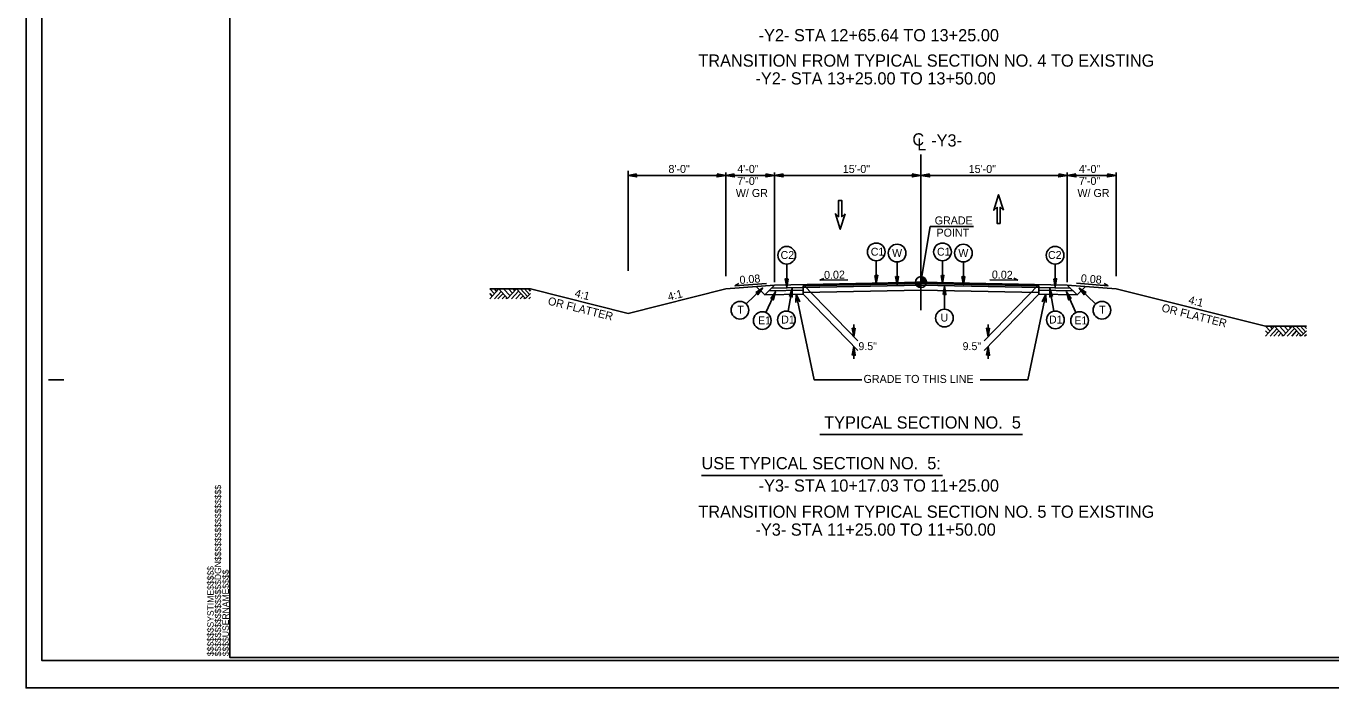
# Model space of a CAD drawing. Extents: x 1901718 to 1902220, y 193828 to 194187.
# Drawn here: x 1901965.8 to 1902072.8, y 193828 to 193882.3 of the extents above; entities that cross this region are included whole.
import ezdxf

# ---------------------------------------------------------------- set-up
doc = ezdxf.new("R2010")
doc.units = 0
for name, color, linetype in [('Old_Level_1', 7, 'Continuous'), ('Old_Level_11', 7, 'Continuous'), ('Old_Level_2', 7, 'Continuous'), ('Old_Level_20', 7, 'Continuous'), ('Old_Level_3', 7, 'Continuous'), ('Prop Dimension', 7, 'Continuous'), ('Sheet Border Standard 30in CELL', 7, 'Continuous'), ('Sheet Cutting Line CELL', 7, 'Continuous'), ('Sheet Plot Border Inside CELL', 7, 'Continuous'), ('Sheet Plot Border Outside CELL', 7, 'Continuous'), ('Typical Terminator CELL', 7, 'Continuous')]:
    doc.layers.add(name, color=color, linetype=linetype)

# ---------------------------------------------------------------- blocks, each defined once
blk = doc.blocks.new('TERMINATOR')
at = {"layer": 'Typical Terminator CELL'}
blk.add_lwpolyline([(-0.469, 0.081), (0, 0), (-0.471, -0.083), (-0.411, 0)], close=True, dxfattribs=at)

msp = doc.modelspace()

# ---------------------------------------------------------------- linework, layer by layer
at = {"layer": 'Old_Level_1'}
for p, q in [((1902039.18, 193858.97), (1902039.18, 193871.72)), ((1902015.18, 193870.02), (1902023.18, 193870.02)), ((1902023.18, 193861.77), (1902023.18, 193870.27)), ((1902023.18, 193870.02), (1902027.18, 193870.02)), ((1902027.18, 193861.27), (1902027.18, 193870.27)), ((1902027.18, 193870.02), (1902039.18, 193870.02)), ((1902051.18, 193870.02), (1902039.18, 193870.02)), ((1902051.18, 193861.27), (1902051.18, 193870.27)), ((1902055.18, 193870.02), (1902051.18, 193870.02)), ((1902055.18, 193861.77), (1902055.18, 193870.27)), ((1902027.18, 193861.03), (1902023.18, 193860.71)), ((1902026.52, 193861.17), (1902023.94, 193860.97)), ((1902023.94, 193860.97), (1902024.26, 193861.15)), ((1902026.38, 193860.23), (1902025.69, 193860.92)), ((1902027.18, 193861.03), (1902026.38, 193860.23)), ((1902029.53, 193860.83), (1902026.93, 193860.78)), ((1902039.18, 193861.27), (1902027.18, 193861.03)), ((1902039.18, 193861.17), (1902029.53, 193860.98)), ((1902029.53, 193861.08), (1902034, 193856.46)), ((1902039.18, 193861.02), (1902029.53, 193860.83)), ((1902029.53, 193860.98), (1902029.53, 193860.29)), ((1902030.9, 193861.42), (1902031.23, 193861.58)), ((1902033.2, 193861.46), (1902030.9, 193861.42)), ((1902038.73, 193861.27), (1902039.18, 193861.27)), ((1902039.18, 193861.27), (1902039.18, 193861.72)), ((1902039.63, 193861.27), (1902039.18, 193861.27)), ((1902039.18, 193860.82), (1902039.18, 193861.27)), ((1902039.18, 193861.27), (1902039.18, 193860.82)), ((1902039.18, 193861.27), (1902051.18, 193861.03)), ((1902039.18, 193861.17), (1902048.84, 193860.98)), ((1902039.18, 193861.02), (1902048.84, 193860.83)), ((1902048.84, 193861.08), (1902044.36, 193856.46)), ((1902044.82, 193861.46), (1902047.12, 193861.42)), ((1902047.12, 193861.42), (1902046.8, 193861.6)), ((1902048.84, 193860.98), (1902048.84, 193860.29)), ((1902048.84, 193860.83), (1902051.44, 193860.78)), ((1902051.18, 193861.03), (1902055.18, 193860.71)), ((1902051.99, 193860.23), (1902051.18, 193861.03)), ((1902051.94, 193861.18), (1902054.52, 193860.97)), ((1902051.99, 193860.23), (1902052.68, 193860.92)), ((1902054.52, 193860.97), (1902054.2, 193861.16)), ((1902003.84, 193859.91), (1902004.58, 193860.71)), ((1902003.84, 193860.71), (1902004.22, 193860.31)), ((1902003.84, 193860.35), (1902004.05, 193860.13)), ((1902004.22, 193860.71), (1902004.4, 193860.51)), ((1902004.22, 193859.91), (1902004.77, 193860.51)), ((1902004.52, 193859.91), (1902004.93, 193860.34)), ((1902004.58, 193860.71), (1902005.31, 193859.93)), ((1902004.87, 193859.91), (1902005.1, 193860.15)), ((1902004.97, 193860.71), (1902005.51, 193860.14)), ((1902005.18, 193859.91), (1902005.25, 193859.99)), ((1902005.31, 193859.93), (1902006.04, 193860.71)), ((1902005.37, 193860.71), (1902005.71, 193860.36)), ((1902005.62, 193859.91), (1902006.2, 193860.54)), ((1902005.77, 193860.71), (1902005.91, 193860.57)), ((1902005.99, 193859.91), (1902006.39, 193860.34)), ((1902006.04, 193860.71), (1902006.78, 193859.92)), ((1902006.35, 193859.91), (1902006.57, 193860.14)), ((1902006.36, 193860.71), (1902006.94, 193860.09)), ((1902006.65, 193859.91), (1902006.72, 193859.98)), ((1902006.69, 193860.71), (1902007.11, 193860.27)), ((1902006.78, 193859.92), (1902007.18, 193860.35)), ((1902007.01, 193860.71), (1902007.18, 193860.53)), ((1902007.05, 193859.91), (1902007.18, 193860.05)), ((1902007.18, 193860.71), (1902015.18, 193858.71)), ((1902023.18, 193860.71), (1902015.18, 193858.71)), ((1902029.53, 193860.29), (1902026.38, 193860.23)), ((1902029.53, 193860.62), (1902026.72, 193860.57)), ((1902029.53, 193860.29), (1902034, 193855.67)), ((1902039.18, 193860.61), (1902029.54, 193860.42)), ((1902039.18, 193860.61), (1902048.83, 193860.42)), ((1902048.84, 193860.29), (1902044.36, 193855.67)), ((1902048.84, 193860.62), (1902051.65, 193860.57)), ((1902048.84, 193860.29), (1902051.99, 193860.23)), ((1902055.18, 193860.71), (1902067.43, 193857.65)), ((1902033.68, 193857.79), (1902033.68, 193856.79)), ((1902044.68, 193857.79), (1902044.68, 193856.79)), ((1902033.68, 193855.99), (1902033.68, 193854.99)), ((1902044.68, 193855.99), (1902044.68, 193854.99))]:
    msp.add_line(p, q, dxfattribs=at)
for points in [[(1902038.74, 193861.27), (1902038.74, 193861.23)], [(1902038.74, 193861.27), (1902038.74, 193861.17)], [(1902038.75, 193861.27), (1902038.75, 193861.14)], [(1902038.76, 193861.27), (1902038.76, 193861.11)], [(1902038.77, 193861.27), (1902038.77, 193861.09)], [(1902038.78, 193861.27), (1902038.78, 193861.07)], [(1902038.79, 193861.27), (1902038.79, 193861.06)], [(1902038.8, 193861.27), (1902038.8, 193861.04)], [(1902038.81, 193861.27), (1902038.81, 193861.03)], [(1902038.82, 193861.27), (1902038.82, 193861.01)], [(1902038.83, 193861.27), (1902038.83, 193861)], [(1902038.83, 193861.27), (1902038.83, 193860.99)], [(1902038.84, 193861.27), (1902038.84, 193860.98)], [(1902038.85, 193861.27), (1902038.85, 193860.97)], [(1902038.86, 193861.27), (1902038.86, 193860.96)], [(1902038.87, 193861.27), (1902038.87, 193860.95)], [(1902038.88, 193861.27), (1902038.88, 193860.94)], [(1902038.89, 193861.27), (1902038.89, 193860.93)], [(1902038.9, 193861.27), (1902038.9, 193860.93)], [(1902038.91, 193861.27), (1902038.91, 193860.92)], [(1902038.92, 193861.27), (1902038.92, 193860.91)], [(1902038.92, 193861.27), (1902038.92, 193860.91)], [(1902038.93, 193861.27), (1902038.93, 193860.9)], [(1902038.94, 193861.27), (1902038.94, 193860.89)], [(1902038.95, 193861.27), (1902038.95, 193860.89)], [(1902038.96, 193861.27), (1902038.96, 193860.88)], [(1902038.97, 193861.27), (1902038.97, 193860.88)], [(1902038.98, 193861.27), (1902038.98, 193860.87)], [(1902038.99, 193861.27), (1902038.99, 193860.87)], [(1902039, 193861.27), (1902039, 193860.87)], [(1902039.01, 193861.27), (1902039.01, 193860.86)], [(1902039.01, 193861.27), (1902039.01, 193860.86)], [(1902039.02, 193861.27), (1902039.02, 193860.85)], [(1902039.03, 193861.27), (1902039.03, 193860.85)], [(1902039.04, 193861.27), (1902039.04, 193860.85)], [(1902039.05, 193861.27), (1902039.05, 193860.84)], [(1902039.06, 193861.27), (1902039.06, 193860.84)], [(1902039.07, 193861.27), (1902039.07, 193860.84)], [(1902039.08, 193861.27), (1902039.08, 193860.84)], [(1902039.09, 193861.27), (1902039.09, 193860.84)], [(1902039.1, 193861.27), (1902039.1, 193860.83)], [(1902039.1, 193861.27), (1902039.1, 193860.83)], [(1902039.11, 193861.27), (1902039.11, 193860.83)], [(1902039.12, 193861.27), (1902039.12, 193860.83)], [(1902039.13, 193861.27), (1902039.13, 193860.83)], [(1902039.14, 193861.27), (1902039.14, 193860.83)], [(1902039.15, 193861.27), (1902039.15, 193860.83)], [(1902039.16, 193861.27), (1902039.16, 193860.83)], [(1902039.17, 193861.27), (1902039.17, 193860.82)], [(1902039.18, 193861.27), (1902039.18, 193860.82), (1902039.18, 193860.82)], [(1902039.19, 193861.72), (1902039.19, 193861.72), (1902039.19, 193861.27)], [(1902039.2, 193861.72), (1902039.2, 193861.27)], [(1902039.21, 193861.72), (1902039.21, 193861.27)], [(1902039.21, 193861.72), (1902039.21, 193861.27)], [(1902039.22, 193861.72), (1902039.22, 193861.27)], [(1902039.23, 193861.72), (1902039.23, 193861.27)], [(1902039.24, 193861.72), (1902039.24, 193861.27)], [(1902039.25, 193861.72), (1902039.25, 193861.27)], [(1902039.26, 193861.72), (1902039.26, 193861.27)], [(1902039.27, 193861.72), (1902039.27, 193861.27)], [(1902039.28, 193861.71), (1902039.28, 193861.27)], [(1902039.29, 193861.71), (1902039.29, 193861.27)], [(1902039.3, 193861.71), (1902039.3, 193861.27)], [(1902039.3, 193861.71), (1902039.3, 193861.27)], [(1902039.31, 193861.71), (1902039.31, 193861.27)], [(1902039.32, 193861.7), (1902039.32, 193861.27)], [(1902039.33, 193861.7), (1902039.33, 193861.27)], [(1902039.34, 193861.7), (1902039.34, 193861.27)], [(1902039.35, 193861.69), (1902039.35, 193861.27)], [(1902039.36, 193861.69), (1902039.36, 193861.27)], [(1902039.37, 193861.68), (1902039.37, 193861.27)], [(1902039.38, 193861.68), (1902039.38, 193861.27)], [(1902039.39, 193861.68), (1902039.39, 193861.27)], [(1902039.39, 193861.67), (1902039.39, 193861.27)], [(1902039.4, 193861.67), (1902039.4, 193861.27)], [(1902039.41, 193861.66), (1902039.41, 193861.27)], [(1902039.42, 193861.66), (1902039.42, 193861.27)], [(1902039.43, 193861.65), (1902039.43, 193861.27)], [(1902039.44, 193861.64), (1902039.44, 193861.27)], [(1902039.45, 193861.64), (1902039.45, 193861.27)], [(1902039.46, 193861.63), (1902039.46, 193861.27)], [(1902039.47, 193861.62), (1902039.47, 193861.27)], [(1902039.48, 193861.62), (1902039.48, 193861.27)], [(1902039.48, 193861.61), (1902039.48, 193861.27)], [(1902039.49, 193861.6), (1902039.49, 193861.27)], [(1902039.5, 193861.59), (1902039.5, 193861.27)], [(1902039.51, 193861.58), (1902039.51, 193861.27)], [(1902039.52, 193861.57), (1902039.52, 193861.27)], [(1902039.53, 193861.56), (1902039.53, 193861.27)], [(1902039.54, 193861.55), (1902039.54, 193861.27)], [(1902039.55, 193861.54), (1902039.55, 193861.27)], [(1902039.56, 193861.53), (1902039.56, 193861.27)], [(1902039.57, 193861.51), (1902039.57, 193861.27)], [(1902039.57, 193861.5), (1902039.57, 193861.27)], [(1902039.58, 193861.48), (1902039.58, 193861.27)], [(1902039.59, 193861.46), (1902039.59, 193861.27)], [(1902039.6, 193861.44), (1902039.6, 193861.27)], [(1902039.61, 193861.42), (1902039.61, 193861.27)], [(1902039.62, 193861.38), (1902039.62, 193861.27)], [(1902039.63, 193861.34), (1902039.63, 193861.27)], [(1902003.84, 193860.71), (1902007.18, 193860.71)], [(1902029.25, 193859.67), (1902028.96, 193860.28), (1902028.93, 193859.6)], [(1902028.96, 193860.28), (1902030.42, 193853.27), (1902034.33, 193853.27)], [(1902049.41, 193860.28), (1902047.95, 193853.27), (1902044.04, 193853.27)], [(1902049.12, 193859.67), (1902049.41, 193860.28), (1902049.44, 193859.6)], [(1902067.43, 193857.65), (1902070.77, 193857.65)]]:
    msp.add_lwpolyline(points, dxfattribs=at)
msp.add_circle((1902039.18, 193861.27), 0.45, dxfattribs=at)
for start, end in [(179.9905, 269.9905), (359.9905, 89.9905)]:
    msp.add_arc((1902039.18, 193861.27), 0.45, start, end, dxfattribs=at)
at = {"layer": 'Old_Level_11'}
for p, q in [((1902035.52, 193863.02), (1902035.52, 193861.15)), ((1902037.23, 193862.93), (1902037.23, 193861.05)), ((1902040.95, 193863.02), (1902040.95, 193861.15)), ((1902042.66, 193862.93), (1902042.66, 193861.05)), ((1902028.18, 193862.75), (1902028.18, 193860.87)), ((1902050.18, 193862.75), (1902050.18, 193860.87)), ((1902024.87, 193859.48), (1902026.2, 193860.79)), ((1902028.29, 193858.9), (1902028.63, 193860.74)), ((1902041.11, 193859.05), (1902041.11, 193860.93)), ((1902050.07, 193858.9), (1902049.74, 193860.74)), ((1902053.5, 193859.48), (1902052.16, 193860.79)), ((1902026.48, 193858.77), (1902027.26, 193860.48)), ((1902051.89, 193858.77), (1902051.1, 193860.48)), ((1902067.43, 193856.85), (1902068.17, 193857.65)), ((1902067.43, 193857.65), (1902067.8, 193857.25)), ((1902067.8, 193857.65), (1902067.99, 193857.45)), ((1902068.17, 193857.65), (1902068.89, 193856.87)), ((1902068.56, 193857.65), (1902069.09, 193857.08)), ((1902068.89, 193856.87), (1902069.62, 193857.65)), ((1902068.96, 193857.65), (1902069.29, 193857.3)), ((1902069.36, 193857.65), (1902069.49, 193857.51)), ((1902069.62, 193857.65), (1902070.36, 193856.86)), ((1902069.95, 193857.65), (1902070.53, 193857.03)), ((1902070.28, 193857.65), (1902070.69, 193857.21)), ((1902070.6, 193857.65), (1902070.77, 193857.47)), ((1902067.43, 193857.29), (1902067.63, 193857.07)), ((1902067.8, 193856.85), (1902068.35, 193857.45)), ((1902068.11, 193856.85), (1902068.51, 193857.28)), ((1902068.46, 193856.85), (1902068.68, 193857.09)), ((1902068.77, 193856.85), (1902068.84, 193856.93)), ((1902069.2, 193856.85), (1902069.79, 193857.48)), ((1902069.57, 193856.85), (1902069.97, 193857.28)), ((1902069.94, 193856.85), (1902070.16, 193857.08)), ((1902070.23, 193856.85), (1902070.3, 193856.92)), ((1902070.36, 193856.86), (1902070.77, 193857.29)), ((1902070.63, 193856.85), (1902070.77, 193856.99)), ((1902030.89, 193848.77), (1902047.52, 193848.77)), ((1902021.2, 193845.43), (1902040.94, 193845.43))]:
    msp.add_line(p, q, dxfattribs=at)
for points in [[(1902035.4, 193861.82), (1902035.52, 193861.15), (1902035.64, 193861.83), (1902035.52, 193861.74)], [(1902040.83, 193861.82), (1902040.95, 193861.15), (1902041.07, 193861.83), (1902040.95, 193861.74)], [(1902025.64, 193860.41), (1902026.2, 193860.79), (1902025.81, 193860.24), (1902025.78, 193860.38)], [(1902028.3, 193861.55), (1902028.18, 193860.87), (1902028.06, 193861.55), (1902028.18, 193861.46)], [(1902028.4, 193860.1), (1902028.63, 193860.74), (1902028.63, 193860.05), (1902028.53, 193860.16)], [(1902037.11, 193861.72), (1902037.23, 193861.05), (1902037.35, 193861.73), (1902037.23, 193861.64)], [(1902041, 193860.26), (1902041.11, 193860.93), (1902041.23, 193860.25), (1902041.11, 193860.34)], [(1902042.54, 193861.72), (1902042.66, 193861.05), (1902042.78, 193861.73), (1902042.66, 193861.64)], [(1902049.97, 193860.1), (1902049.74, 193860.74), (1902049.74, 193860.05), (1902049.84, 193860.16)], [(1902050.07, 193861.55), (1902050.18, 193860.87), (1902050.3, 193861.55), (1902050.18, 193861.46)], [(1902052.72, 193860.41), (1902052.16, 193860.79), (1902052.56, 193860.24), (1902052.58, 193860.38)], [(1902026.88, 193859.92), (1902027.26, 193860.48), (1902027.09, 193859.81), (1902027.02, 193859.94)], [(1902051.49, 193859.92), (1902051.1, 193860.48), (1902051.28, 193859.81), (1902051.35, 193859.94)]]:
    msp.add_lwpolyline(points, close=True, dxfattribs=at)
for centre in [(1902028.18, 193863.47), (1902035.52, 193863.75), (1902037.23, 193863.65), (1902040.95, 193863.75), (1902042.66, 193863.65), (1902050.18, 193863.47), (1902024.35, 193858.97), (1902054.02, 193858.97), (1902026.18, 193858.12), (1902028.16, 193858.18), (1902041.11, 193858.33), (1902050.2, 193858.18), (1902052.19, 193858.12)]:
    msp.add_circle(centre, 0.725, dxfattribs=at)
at = {"layer": 'Old_Level_3'}
for q in [(1902039.18, 193861.27), (1902043.5, 193865.84)]:
    msp.add_line((1902039.93, 193865.84), q, dxfattribs=at)
at = {"layer": 'Prop Dimension'}
msp.add_line((1902015.18, 193862.2), (1902015.18, 193870.39), dxfattribs=at)
for points in [[(1902045.94, 193867.16), (1902045.67, 193867.41), (1902045.67, 193866.08), (1902045.42, 193866.08), (1902045.42, 193867.41), (1902045.15, 193867.16), (1902045.54, 193868.43)], [(1902045.94, 193867.16), (1902045.67, 193867.41), (1902045.67, 193866.08), (1902045.42, 193866.08), (1902045.42, 193867.41), (1902045.15, 193867.16), (1902045.54, 193868.43)], [(1902032.96, 193866.88), (1902032.69, 193866.63), (1902032.69, 193867.97), (1902032.44, 193867.97), (1902032.44, 193866.63), (1902032.17, 193866.88), (1902032.57, 193865.61)], [(1902032.96, 193866.88), (1902032.69, 193866.63), (1902032.69, 193867.97), (1902032.44, 193867.97), (1902032.44, 193866.63), (1902032.17, 193866.88), (1902032.57, 193865.61)]]:
    msp.add_lwpolyline(points, close=True, dxfattribs=at)
at = {"layer": 'Sheet Border Standard 30in CELL'}
msp.add_line((1901967.69, 193853.26), (1901968.94, 193853.26), dxfattribs=at)
msp.add_lwpolyline([(1902132.54, 193935.51), (1901982.54, 193935.51), (1901982.54, 193830.51), (1902132.54, 193830.51)], close=True, dxfattribs=at)
at = {"layer": 'Sheet Cutting Line CELL'}
for p, q in [((1901965.84, 193938.01), (1901965.84, 193828.01)), ((1901965.84, 193828.01), (1902134.24, 193828.01))]:
    msp.add_line(p, q, dxfattribs=at)
at = {"layer": 'Sheet Plot Border Inside CELL'}
msp.add_lwpolyline([(1902133.79, 193935.77), (1901967.14, 193935.77), (1901967.14, 193830.26), (1902133.79, 193830.26)], close=True, dxfattribs=at)
at = {"layer": 'Sheet Plot Border Outside CELL'}
msp.add_lwpolyline([(1902134.24, 193938.01), (1901965.84, 193938.01), (1901965.84, 193828.01), (1902134.24, 193828.01)], close=True, dxfattribs=at)

# ---------------------------------------------------------------- block references
at = {"layer": 'Old_Level_1', "xscale": 1.5, "yscale": 1.5}
for p, rotation in [((1902033.68, 193856.79), -90), ((1902044.68, 193856.79), -90), ((1902033.68, 193855.99), 90), ((1902044.68, 193855.99), 90)]:
    msp.add_blockref('TERMINATOR', p, dxfattribs=dict(at, rotation=rotation))
at = {"layer": 'Prop Dimension', "xscale": 1.5, "yscale": -1.5, "rotation": 180}
for p in [(1902015.18, 193870.02), (1902023.18, 193870.02), (1902027.18, 193870.02), (1902039.18, 193870.02), (1902051.18, 193870.02)]:
    msp.add_blockref('TERMINATOR', p, dxfattribs=at)
at = {"layer": 'Prop Dimension', "xscale": 1.5, "yscale": 1.5}
for p in [(1902023.18, 193870.02), (1902027.18, 193870.02), (1902039.18, 193870.02), (1902051.18, 193870.02), (1902055.18, 193870.02)]:
    msp.add_blockref('TERMINATOR', p, dxfattribs=at)

# ---------------------------------------------------------------- texts
at = {"layer": 'Old_Level_1'}
for s, p in [('8\'-0"', (1902018.49, 193870.22)), ('15\'-0" ', (1902032.78, 193870.22)), ('15\'-0" ', (1902043.1, 193870.22)), ('4\'-0"', (1902052.13, 193870.22)), ('7\'-0"', (1902052.13, 193869.24)), ('W/ GR', (1902052.01, 193868.25)), ('GRADE TO THIS LINE', (1902034.48, 193853.01))]:
    msp.add_text(s, height=0.656, dxfattribs=at).set_placement(p)
for s, rotation, p in [('4\'-0"', 360, (1902024.13, 193870.22)), ('7\'-0"', 360, (1902024.13, 193869.24)), ('W/ GR', 360, (1902024.01, 193868.25)), ('OR FLATTER', 345.9638, (1902008.56, 193859.44)), ('4:1', 345.9638, (1902010.76, 193860.08)), ('4:1', 14.0362, (1902018.52, 193859.74)), ('4:1', 345.9638, (1902061.06, 193859.53)), ('OR FLATTER', 345.9638, (1902058.86, 193858.88))]:
    msp.add_text(s, height=0.656, rotation=rotation, dxfattribs=at).set_placement(p)
at = {"layer": 'Old_Level_11'}
for s, height, p in [('-Y2- STA 12+65.64 TO 13+25.00', 1, (1902025.88, 193881.01)), ('TRANSITION FROM TYPICAL SECTION NO. 4 TO EXISTING', 1, (1902020.94, 193878.93)), ('-Y2- STA 13+25.00 TO 13+50.00', 1, (1902025.62, 193877.47)), ('GRADE', 0.656, (1902040.31, 193866)), ('POINT', 0.656, (1902040.46, 193865)), ('TYPICAL SECTION NO.  5', 1, (1902031.25, 193849.27)), ('USE TYPICAL SECTION NO.  5:', 1, (1902021.2, 193845.93)), ('-Y3- STA 10+17.03 TO 11+25.00', 1, (1902025.88, 193844.1)), ('TRANSITION FROM TYPICAL SECTION NO. 5 TO EXISTING', 1, (1902020.94, 193841.96)), ('-Y3- STA 11+25.00 TO 11+50.00', 1, (1902025.62, 193840.49))]:
    msp.add_text(s, height=height, dxfattribs=at).set_placement(p)
at = {"layer": 'Old_Level_2'}
msp.add_text('C', height=1, dxfattribs=at).set_placement((1902038.48, 193872.47))
for s, height, rotation, p in [('L', 1, 359.9469, (1902038.88, 193872.07)), ('-Y3-', 1, 359.9469, (1902040.02, 193872.39)), ('0.08', 0.656, 4.5739, (1902024.34, 193861.12)), ('0.02', 0.656, 1.1916, (1902031.25, 193861.53)), ('0.02', 0.656, 358.8084, (1902044.99, 193861.57)), ('0.08', 0.656, 355.4261, (1902052.27, 193861.27))]:
    msp.add_text(s, height=height, rotation=rotation, dxfattribs=at).set_placement(p)
at = {"layer": 'Old_Level_20'}
for s, p in [('C1', (1902035.07, 193863.44)), ('W', (1902036.82, 193863.34)), ('C1', (1902040.5, 193863.44)), ('W', (1902042.25, 193863.34)), ('C2', (1902027.68, 193863.17)), ('C2', (1902049.6, 193863.17)), ('U', (1902040.79, 193858.04)), ('T', (1902053.79, 193858.68)), ('E1', (1902025.83, 193857.81)), ('D1', (1902027.73, 193857.88)), ('D1', (1902049.68, 193857.88)), ('E1', (1902051.76, 193857.81)), ('9.5"', (1902034.06, 193855.7)), ('9.5"', (1902042.6, 193855.7))]:
    msp.add_text(s, height=0.649, dxfattribs=at).set_placement(p)
msp.add_text('T', height=0.649, rotation=360, dxfattribs=at).set_placement((1902024.14, 193858.68))
at = {"layer": 'Sheet Border Standard 30in CELL'}
for s, p in [('$$$$$$$$$$$$$$$$DGN$$$$$$$$$$$$$$$$', (1901981.83, 193830.6)), ('$$$$$$SYSTIME$$$$$', (1901981.22, 193830.62)), ('$$$$USERNAME$$$$', (1901982.46, 193830.61))]:
    msp.add_text(s, height=0.525, rotation=90, dxfattribs=at).set_placement(p)

doc.saveas('drawing.dxf')
